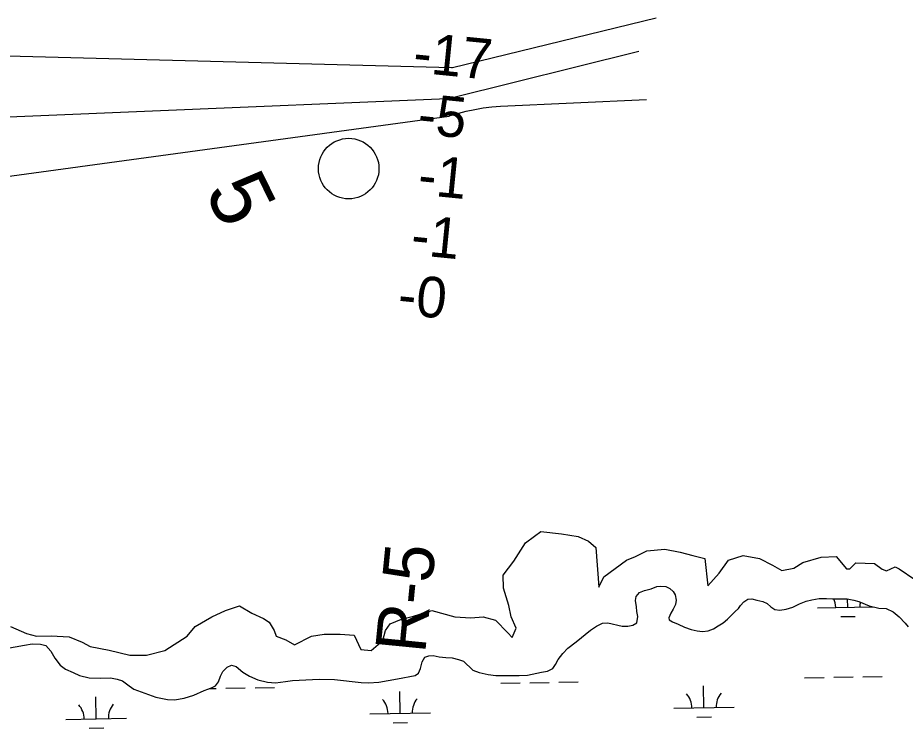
# Model space of a CAD drawing. Extents: x 3957609 to 3995875, y 234277 to 260273.
# Drawn here: x 3970170 to 3971636, y 245185 to 246359 of the extents above; entities that cross this region are included whole.
import ezdxf

# ---------------------------------------------------------------- set-up
doc = ezdxf.new("R2010")
doc.units = 0
for name, color, linetype in [('V-RIVR-EDGE', 7, 'Continuous'), ('V-RIVR-IDEN', 7, 'Continuous'), ('V-RIVR-MILE', 7, 'Continuous'), ('V-RIVR-RANG', 7, 'Continuous'), ('V-RIVR-RANG-IDEN', 7, 'Continuous'), ('V-TOPO-MINR', 7, 'Continuous'), ('V-WETL-SWMP', 7, 'Continuous')]:
    doc.layers.add(name, color=color, linetype=linetype)

msp = doc.modelspace()

# ---------------------------------------------------------------- linework, layer by layer
at = {"layer": 'V-RIVR-EDGE'}
for points in [[(3970556.717, 245375.211), (3970575.646, 245366.108), (3970585.114, 245360.426), (3970593.636, 245346.223), (3970596.477, 245336.755), (3970612.573, 245331.074), (3970626.776, 245322.552), (3970655.182, 245336.755), (3970676.013, 245340.542), (3970702.525, 245340.542), (3970725.25, 245338.648), (3970736.613, 245314.977), (3970753.656, 245313.083), (3970772.593, 245330.127), (3970777.328, 245346.223), (3970784.903, 245357.586), (3970803.84, 245365.161), (3970823.724, 245369.895), (3970854.024, 245379.364), (3970891.898, 245368.948), (3970918.411, 245367.054), (3970938.295, 245368.948), (3970959.126, 245363.267), (3970979.01, 245342.436), (3970986.585, 245334.861), (3970993.213, 245350.011), (3970984.691, 245368.948), (3970980.904, 245387.885), (3970972.382, 245416.291), (3970971.435, 245438.069), (3970989.426, 245460.794), (3971008.363, 245491.094), (3971023.513, 245502.456), (3971033.928, 245510.031), (3971068.015, 245506.244), (3971095.474, 245501.509), (3971112.518, 245493.934), (3971124.827, 245483.519), (3971129.562, 245418.185), (3971138.083, 245435.229), (3971175.011, 245462.688), (3971190.161, 245468.369), (3971209.098, 245477.838), (3971238.451, 245480.678), (3971264.016, 245475.944), (3971284.847, 245470.263), (3971304.732, 245465.528), (3971309.466, 245420.079), (3971328.403, 245440.91), (3971343.553, 245462.688), (3971368.172, 245470.263), (3971394.684, 245465.528), (3971416.462, 245454.166), (3971431.612, 245445.644), (3971451.496, 245449.432), (3971466.646, 245458.9), (3971496.945, 245467.422), (3971521.564, 245468.369), (3971538.607, 245448.485), (3971544.288, 245448.485), (3971553.757, 245457.953), (3971585.004, 245457.007), (3971597.313, 245447.538), (3971604.888, 245444.697), (3971619.091, 245451.325), (3971625.719, 245448.485), (3971651.284, 245430.494)], [(3970158.078, 245352.851), (3970184.59, 245341.489), (3970200.687, 245336.755), (3970225.305, 245337.702), (3970254.658, 245335.808), (3970276.436, 245327.286), (3970289.692, 245319.711), (3970320.939, 245314.03), (3970355.026, 245305.508), (3970382.485, 245305.508), (3970412.785, 245313.083), (3970449.712, 245336.755), (3970462.969, 245352.851), (3970490.428, 245368.948), (3970513.152, 245379.364), (3970535.877, 245386.939), (3970556.781, 245375.146)]]:
    msp.add_lwpolyline(points, dxfattribs=at)
at = {"layer": 'V-RIVR-MILE'}
msp.add_circle((3970716.464, 246109.504), 50, dxfattribs=at)
at = {"layer": 'V-TOPO-MINR'}
for points in [[(3968018.214, 246314.387), (3968169.95, 246323.752), (3968183.086, 246324.466), (3968196.227, 246325.051), (3968209.375, 246325.442), (3968222.528, 246325.705), (3968477.968, 246328.931), (3968618.838, 246329.888), (3968759.702, 246329.746), (3968900.553, 246327.959), (3969041.398, 246325.074), (3970886.166, 246276.501), (3970886.6, 246276.508), (3970887.46, 246276.621), (3970887.884, 246276.714), (3971224.276, 246358.726)], [(3967984.26, 246085.689), (3968092.213, 246090.995), (3968141.873, 246093.558), (3968191.524, 246096.284), (3968241.162, 246099.254), (3968290.79, 246102.387), (3968851.891, 246139.195), (3968877.6, 246141.493), (3970879.56, 246225.354), (3970881.146, 246225.397), (3970884.286, 246225.855), (3970885.836, 246226.204), (3971195.807, 246303.452)], [(3967993.694, 245839.928), (3968037.136, 245840.981), (3968087.474, 245842.556), (3968178.984, 245845.901), (3968183.56, 245846.084), (3968188.135, 245846.289), (3968192.709, 245846.525), (3968197.281, 245846.782), (3968292.438, 245852.461), (3968344.567, 245855.838), (3968396.67, 245859.567), (3968448.732, 245863.824), (3970882.382, 246196.277), (3970883.256, 246197.118), (3970883.849, 246197.376), (3970910.475, 246204.139), (3970924.528, 246207.257), (3970938.667, 246209.799), (3970952.935, 246211.476), (3970967.288, 246212.578), (3971208.52, 246223.719)]]:
    msp.add_lwpolyline(points, dxfattribs=at)
at = {"layer": 'V-WETL-SWMP'}
for p, q in [((3971540.727, 245384.983), (3971540.485, 245398.291)), ((3971490.735, 245384.074), (3971581.896, 245385.731)), ((3971529.01, 245369.336), (3971553.006, 245369.773)), ((3971469.43, 245268.235), (3971501.425, 245268.817)), ((3971517.422, 245269.108), (3971549.417, 245269.69)), ((3971565.414, 245269.981), (3971597.409, 245270.562)), ((3970485.923, 245250.352), (3970497.774, 245250.568)), ((3970513.772, 245250.859), (3970545.766, 245251.44)), ((3970561.764, 245251.731), (3970593.759, 245252.313)), ((3970967.605, 245259.111), (3970999.599, 245259.692)), ((3971015.597, 245259.983), (3971047.592, 245260.565)), ((3971063.589, 245260.856), (3971095.584, 245261.438)), ((3971303.238, 245218.776), (3971302.583, 245254.77)), ((3970299.587, 245200.526), (3970298.933, 245236.52)), ((3970801.412, 245209.651), (3970800.758, 245245.645)), ((3970751.421, 245208.742), (3970851.404, 245210.56)), ((3971253.246, 245217.867), (3971353.229, 245219.685)), ((3970249.596, 245199.617), (3970349.579, 245201.435)), ((3970789.695, 245194.005), (3970813.691, 245194.441)), ((3971291.52, 245203.129), (3971315.516, 245203.566)), ((3970287.87, 245184.88), (3970311.866, 245185.316))]:
    msp.add_line(p, q, dxfattribs=at)
for points in [[(3970489.781, 245251.861), (3970496.498, 245254.867), (3970501.252, 245261.627), (3970504.805, 245271.197), (3970508.482, 245278.593), (3970515.882, 245285.934), (3970523.065, 245288.934), (3970530.481, 245286.654), (3970541.834, 245277.643), (3970552.601, 245270.968), (3970566.477, 245264.714), (3970582.409, 245261.069), (3970595.431, 245260.104), (3970611.909, 245262.037), (3970623.884, 245263.725), (3970667.836, 245266.036), (3970693.125, 245265.513), (3970736.812, 245260.223), (3970749.382, 245260.196), (3970766.466, 245261.034), (3970797.118, 245266.486), (3970826.373, 245271.958), (3970831.865, 245276.069), (3970834.923, 245283.629), (3970837.721, 245294.607), (3970842.333, 245302.299), (3970849.041, 245304.685), (3970856.185, 245305.047), (3970866.086, 245302.885), (3970876.778, 245301.799), (3970887.32, 245301.025), (3970897.995, 245298.697), (3970905.865, 245295.635), (3970921.637, 245280.973), (3970931.668, 245277.102), (3970946.981, 245273.621), (3970959.219, 245272.046), (3970966.819, 245271.781), (3970997.865, 245272.261), (3971011.53, 245272.839), (3971034.873, 245277.311), (3971044.525, 245279.343), (3971053.587, 245283.557), (3971057.871, 245290.013), (3971062.648, 245298.324), (3971070.089, 245308.458), (3971078.598, 245317.336), (3971092.097, 245327.848), (3971115.968, 245347.211), (3971125.84, 245353.74), (3971135.376, 245358.568), (3971144.695, 245359.053), (3971168.202, 245353.436), (3971177.206, 245353.615), (3971185.92, 245355.196), (3971192.491, 245358.825), (3971194.043, 245369.511), (3971192.453, 245377.604), (3971191.639, 245385.685), (3971190.236, 245395.948), (3971190.954, 245402.611), (3971196.945, 245409.042), (3971204.754, 245412.498), (3971216.126, 245415.437), (3971225.179, 245419.03), (3971232.173, 245419.705), (3971240.385, 245418.809), (3971246.706, 245415.924), (3971252.062, 245410.725), (3971255.55, 245405.087), (3971257.445, 245396.679), (3971256.096, 245389.25), (3971252.569, 245381.541), (3971248.436, 245374.773), (3971245.065, 245367.062), (3971245.794, 245363.793), (3971251.487, 245360.451), (3971260.587, 245356.594), (3971271.071, 245351.786), (3971282.035, 245348.058), (3971291.776, 245345.588), (3971300.924, 245344.99), (3971310.096, 245346.098), (3971318.677, 245349.233), (3971326.816, 245353.925), (3971334.648, 245358.933), (3971342.028, 245364.878), (3971354.938, 245377.572), (3971359.98, 245382.775), (3971363.778, 245387.841), (3971369.299, 245393.969), (3971375.879, 245398.218), (3971382.09, 245398.439), (3971390.443, 245396.61), (3971400.495, 245394.136), (3971407.742, 245390.927), (3971413.409, 245385.724), (3971420.166, 245380.814), (3971428.686, 245379.76), (3971438.801, 245381.63), (3971449.712, 245384.886)], [(3971449.712, 245384.886), (3971461.122, 245390.462), (3971472.201, 245394.647), (3971481.079, 245396.846), (3971493.37, 245398.995), (3971505.637, 245399.438), (3971515.715, 245398.826), (3971539.455, 245398.481), (3971550.444, 245396.459), (3971558.791, 245394.165), (3971575.914, 245387.088), (3971592.001, 245383.44), (3971604.254, 245382.952), (3971615.813, 245377.352), (3971625.623, 245368.985), (3971635.405, 245358.6), (3971640.595, 245352.627)], [(3970140.893, 245314.815), (3970181.039, 245322.146), (3970193.948, 245324.132), (3970207.445, 245323.78), (3970216.413, 245321.477), (3970224.661, 245312.356), (3970231.321, 245300.776), (3970239.845, 245289.323), (3970248.903, 245282.518), (3970261.394, 245277.06), (3970271.877, 245272.252), (3970287.8, 245267.986), (3970306.259, 245267.407), (3970323.338, 245267.935), (3970333.862, 245265.92), (3970343.133, 245263.147), (3970354.03, 245254.764), (3970361.556, 245249.378), (3970373.6, 245245.168), (3970398.144, 245236.121), (3970417.33, 245232.118), (3970428.809, 245231.796), (3970444.986, 245234.354), (3970460.889, 245239.4), (3970477.919, 245247.222), (3970489.781, 245251.861)]]:
    msp.add_lwpolyline(points, dxfattribs=at)
for centre, start, end in [((3971485.485, 245384.453), 0.269879, 24.01458), ((3971595.952, 245386.462), 169.124753, 181.813534), ((3971247.995, 245218.246), 0.269879, 41.813537), ((3971358.463, 245220.255), 140.269876, 181.813534), ((3970244.345, 245199.997), 0.269879, 41.813537), ((3970354.813, 245202.005), 140.269876, 181.813534), ((3970746.17, 245209.122), 0.269879, 41.813537), ((3970856.638, 245211.13), 140.269876, 181.813534)]:
    msp.add_arc(centre, 35.246, start, end, dxfattribs=at)

# ---------------------------------------------------------------- texts
at = {"layer": 'V-RIVR-IDEN'}
msp.add_text('5', height=100, rotation=296.179173, dxfattribs=at).set_placement((3970477.89, 246072.009))
at = {"layer": 'V-RIVR-RANG'}
for s, p in [('-17', (3970821.02, 246268.908)), ('-5', (3970828.422, 246167.367)), ('-1', (3970828.958, 246067)), ('-1', (3970817.448, 245967.72)), ('-0', (3970795.69, 245869.308))]:
    msp.add_text(s, height=67, rotation=354.294806, dxfattribs=at).set_placement(p)
at = {"layer": 'V-RIVR-RANG-IDEN'}
msp.add_text('R-5 ', height=83, rotation=84.365732, dxfattribs=at).set_placement((3970842.697, 245307.082))

doc.saveas('drawing.dxf')
